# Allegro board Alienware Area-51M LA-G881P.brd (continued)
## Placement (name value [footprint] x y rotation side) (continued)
PQS10  EMZB08P03H_EDFN5X6-8-5  [AON6403_DFN5X6-8-5]  116.05 164.46 90 top
PQS11  AON6314_N_DFN56-8-5  [Q_N_DFN56-8-5]  150.6 128.97 180 top
PQS12  DMP3056L-7 1P SOT23-3  [NTR4502PT1G_SOT23-3]  113.61 171.48 270 bottom
PQS13  L2N7002DW1T1G_SC88-6  [DMN65D8LDW-7_SOT363-6]  110.84 167.19 0 bottom
PQS15  EMZB08P03H_EDFN5X6-8-5  [AON6403_DFN5X6-8-5]  137.42 150.16 90 top
PQS16  DMP3056L-7 1P SOT23-3  [NTR4502PT1G_SOT23-3]  141.62 152.96 0 bottom
PQS17  L2N7002DW1T1G_SC88-6  [DMN65D8LDW-7_SOT363-6]  147.62 151.53 270 bottom
PQS18  L2N7002WT1G 1N SC-70-3  [SSM3K7002FU_SC70-3]  128.32 152.24 0 top
PQS19  L2N7002WT1G 1N SC-70-3  [SSM3K7002FU_SC70-3]  151.96 147.75 0 top
PQS22  -  [AO3409_SOT23-3]  146.28 158.47 270 bottom
PQS23  L2N7002WT1G 1N SC-70-3  [SSM3K7002FU_SC70-3]  129.12 152.8 270 bottom
PQS24  -  [AO3409_SOT23-3]  160.35 149.98 90 top
PQS26  -  [AO3409_SOT23-3]  142.46 162.46 90 bottom
PQS27  -  [AO3409_SOT23-3]  158.78 156.04 180 top
PQS28  L2N7002WT1G 1N SC-70-3  [SSM3K7002FU_SC70-3]  154.9 152.68 180 top
PQS29  L2N7002DW1T1G_SC88-6  [2N7002DW-7-F_SOT363-6]  124.04 152.42 90 top
PQS30  L2N7002DW1T1G_SC88-6  [2N7002DW-7-F_SOT363-6]  156.34 144.98 0 top
PQS31  -  [LMUN5113T1G_SOT323-3]  126.08 132.52 0 bottom
PQS32  -  [LTC015EUBFS8TL_UMT3F]  128.78 131.48 0 bottom
PR1  100K_0402_1%  [R_0402]  156.25 164.74 180 top
PR2  15K_0402_1%  [R_0402]  154.57 164.75 180 top
PR3  33_0402_5%  [R_0402]  152.04 164.74 90 top
PR4  2.2K_0402_1%  [R_0402]  152.83 165.66 270 top
PR5  10K_0402_1%  [R_0402]  153.04 167.42 180 top
PR6  100K_0402_1%  [R_0402]  134.98 146.16 180 bottom
PR7  15K_0402_1%  [R_0402]  135.99 145.17 270 bottom
PR8  33_0402_5%  [R_0402]  133.07 151.05 180 bottom
PR9  2.2K_0402_1%  [R_0402]  131.47 149.34 90 bottom
PR10  10K_0402_1%  [R_0402]  133.13 146.18 180 bottom
PR11  100_0402_1%  [R_0402]  73.23 10.44 90 top
PR12  100_0402_1%  [R_0402]  72.26 10.44 90 top
PR13  100_0402_1%  [R_0402]  75.75 11.57 0 top
PR14  100K_0402_1%  [R_0402]  77.78 10.06 0 top
PR15  1K_0402_1%  [R_0402]  350.19 13.03 180 top
PR16  100K_0402_1%  [R_0402]  56.41 22.56 90 bottom
PR17  100K_0402_1%  [R_0402]  58.92 21.96 90 bottom
PR18  1K_0402_1%  [R_0402]  352.2 11.28 90 top
PR19  100K_0402_1%  [R_0402]  55.65 22.5 90 bottom
PR20  0_0402_5%  [R0402_0OHM]  58.15 22.88 270 bottom
PR21  100K_0402_1%  [R_0402]  150.78 158.96 0 bottom
PR22  10K_0402_1%  [R_0402]  150 158.09 90 bottom
PR23  110K_0402_1%  [R_0402]  308.2 7.46 270 top
PR24  14.7K_0402_1%  [R_0402]  309.49 27.85 270 top
PR25  14.7K_0402_1%  [R_0402]  300.86 25.57 180 bottom
PR26  100K_0402_1%  [R_0402]  306.48 7.44 270 top
PR27  0_0402_5%  [R0402_0OHM]  151.94 162.66 180 bottom
PR28  100K_0402_1%  [R_0402]  79.1 12.65 90 top
PR34  100K_0402_1%  [R_0402]  59.79 21.15 270 bottom
PR35  205K_0402_1%  [R_0402]  118.01 171.22 90 top
PR36  1M_0402_1%  [R_0402]  117.19 172.13 270 top
PR37  205K_0402_1%  [R_0402]  151.16 152.5 270 top
PR38  1M_0402_1%  [R_0402]  149.43 151.71 0 top
PR40  10K_0402_1%  [R_0402]  149.37 166.16 90 bottom
PR41  100K_0402_1%  [R_0402]  147.37 168.1 180 bottom
PR42  0_0402_5%  [R0402_0OHM]  150.18 165.29 180 bottom
PR44  0_0402_5%  [R0402_0OHM]  155.16 163.85 270 bottom
PR45  0_0402_5%  [R0402_0OHM]  150.64 169.35 90 bottom
PR101  100K_0402_1%  [R_0402]  259.66 10.75 0 top
PR102  2.2_0603_5%  [R_0603]  267.07 10.51 0 top
PR103  97.6K_0402_1%  [R_0402]  259.67 9.98 0 top
PR104  100K_0402_1%  [R_0402]  259.71 8.31 0 top
PR105  4.7_1206_5%  [R_1206]  267.04 17.17 0 bottom
PR106  470K_0402_1%  [R_0402]  261.32 5.61 0 top
PR107  4.99K_0402_1%  [R_0402]  260.61 7.53 180 top
PR108  10K_0402_1%  [R_0402]  260.58 5.93 180 top
PR200  2.2_0603_5%  [R_0603]  217.86 121.4 270 top
PR201  11K_0402_1%  [R_0402]  223.67 118.17 180 top
PR202  4.7_1206_5%  [R_1206]  240.87 113 180 top
PR203  5.1_0603_5%  [R_0603]  223.61 112.67 180 top
PR204  2.2_0603_5%  [R_0603]  223.72 116.96 180 top
PR205  12K_0402_1%  [R_0402]  213.51 115.91 0 top
PR206  887K_0402_1%  [R_0402]  219.36 113.04 90 top
PR207  20K_0402_1%  [R_0402]  213.51 115.14 0 top
PR208  0_0402_5%  [R0402_0OHM]  218.59 112.89 90 top
PR209  0_0402_5%  [R_0402]  216.04 113.78 270 top
PR210  100K_0402_1%  [R_0402]  220.13 113.03 90 top
PR211  0_0402_5%  [R0402_0OHM]  215.26 113.79 270 top
PR212  1K_0402_1%  [R_0402]  217.39 111.16 270 top
PR213  60.4K_0402_1%  [R_0402]  215.02 111.97 270 top
PR214  1K_0402_1%  [R_0402]  214.25 111.97 270 top
PR215  60.4K_0402_1%  [R_0402]  215.79 111.97 270 top
PR216  100K_0402_1%  [R_0402]  216.61 110.25 90 top
PR217  100K_0402_1%  [R_0402]  212.83 108.73 90 top
PR301  10K_0402_1%  [R_0402]  333.04 39.37 180 top
PR302  15.8K_0402_1%  [R_0402]  332.12 36.46 0 top
PR303  14.3K_0402_1%  [R_0402]  333.04 40.13 180 top
PR304  10K_0402_1%  [R_0402]  332.12 37.22 0 top
PR305  54.9K_0402_1%  [R_0402]  333.04 40.93 180 top
PR306  61.9K_0402_1%  [R_0402]  331.29 34.05 90 top
PR307  200_0402_1%  [R_0402]  330.46 34.96 270 top
PR308  0_0603_5%  [R_0603]  328.42 35.15 270 top
PR309  0_0603_5%  [R_0603]  328.41 42.76 270 top
PR310  4.7_1206_5%  [R_1206]  308.77 51.84 270 top
PR311  4.7_1206_5%  [R_1206]  312.69 32.7 180 top
PR312  0_0402_5%  [R0402_0OHM]  326.48 17.05 270 top
PR313  0_0402_5%  [R0402_0OHM]  325.72 17.05 270 top
PR314  2.2K_0402_1%  [R_0402]  324.87 15.34 0 top
PR315  0_0402_5%  [R0402_0OHM]  324.92 13.69 90 top
PR317  200K_0402_1%  [R_0402]  325.68 14.6 270 top
PR703  0.001_2512_1%  [R_2512_4P]  155.75 126.82 180 top
PR727  10.5K_0402_1%  [R_0402]  213.26 143.08 90 top
PR729  392K_0402_1%  [R_0402]  210.08 135.58 90 top
PR731  200K_0402_1%  [R_0402]  210.64 138.33 0 top
PR732  53.6K_0402_1%  [R_0402]  210.97 136.5 270 top
PR740  2_0402_5%  [R_0402]  208.18 132.34 90 top
PR741  100K_0402_1%  [R_0402]  211.43 138.14 180 bottom
PR742  2_0402_5%  [R_0402]  204.93 145.03 90 top
PR743  10_1206_5%  [R_1206]  205.13 133.56 270 top
PR745  100_0402_1%  [R_0402]  204.75 136.19 270 top
PR749  200K_0402_1%  [R_0402]  203.53 143.42 180 top
PR750  0_0402_5%  [R0402_0OHM]  209.03 145.62 0 top
PR751  200K_0402_1%  [R_0402]  202.61 142.65 0 top
PR752  365K_0402_1%  [R_0402]  209.95 146.4 180 top
PR753  255K_0402_1%  [R_0402]  211.24 143.15 180 top
PR754  100_0402_1%  [R_0402]  209.97 144.85 180 top
PR755  102K_0402_1%  [R_0402]  207.73 144.88 270 top
PR756  10K_0402_1%  [R_0402]  206.72 145.74 90 top
PR757  100K_0402_1%  [R_0402]  202.28 143.22 0 bottom
PR760  4.7_0402_5%  [R_0402]  202.46 140.58 270 top
PR761  0_0603_5%  [R0603_0OHM]  200.44 142.64 90 bottom
PR764  10K_0402_1%  [R_0402]  206.72 144.88 270 top
PR765  0.005_2512_1%  [R_2512_4P]  196.01 143.06 0 top
PR766  4.7_1206_5%  [R_1206]  191.67 150.07 90 bottom
PR769  0_0402_5%  [R0402_0OHM]  211.56 139.09 180 top
PR770  0_0402_5%  [R0402_0OHM]  211.56 139.98 180 top
PR771  0_0603_5%  [R_0603]  202.84 137.75 180 top
PR772  1_0402_5%  [R_0402]  208.94 132.34 90 top
PR773  0_0603_5%  [R_0603]  203.29 136.29 180 top
PR774  1K_0402_1%  [R_0402]  211.56 141.25 180 top
PR775  0_0402_5%  [R0402_0OHM]  211.56 142.14 180 top
PR776  0_0402_5%  [R0402_0OHM]  205.75 145.03 90 top
PR777  0_0402_5%  [R0402_0OHM]  213.97 139.98 180 top
PR779  0_0402_5%  [R0402_0OHM]  203.19 144.04 180 bottom
PR792  0_0402_5%  [R0402_0OHM]  212.5 143.99 270 top
PR793  0_0603_5%  [R_0603]  203.71 128.84 270 top
PR1201  40.2K_0402_1%  [R_0402]  352.6 53.29 0 bottom
PR1202  4.7_1206_5%  [R_1206]  360.84 49.99 180 top
PR1203  105K_0402_1%  [R_0402]  354.96 52.42 0 bottom
PR1204  12K_0402_1%  [R_0402]  355.88 51.66 180 bottom
PR1205  100K_0402_1%  [R_0402]  353.52 52.53 180 bottom
PR1206  56K_0402_1%  [R_0402]  355.88 50.67 180 bottom
PR1801  100K_0402_1%  [R_0402]  292.58 34.12 180 bottom
PR1802  1M_0402_1%  [R_0402]  293.15 33.17 180 bottom
PR1803  100K_0402_1%  [R_0402]  293.1 30.45 90 bottom
PR1804  24.9K_0402_1%  [R_0402]  301.42 33.92 270 bottom
PR1805  20K_0402_1%  [R_0402]  301.42 32.26 270 bottom
PR1806  2.2_0402_1%  [R_0402]  239.88 11.78 90 bottom
PR2501  0_0402_5%  [R0402_0OHM]  244.61 18.06 0 bottom
PR2502  1M_0402_1%  [R_0402]  242.94 18.14 270 bottom
PR2503  100K_0402_1%  [R_0402]  242.92 19.77 270 bottom
PR2504  21.5K_0402_1%  [R_0402]  234.63 16.81 90 bottom
PR2505  10K_0402_1%  [R_0402]  234.63 18.45 90 bottom
PR2506  2.2_0402_1%  [R_0402]  240.69 11.78 90 bottom
PRA01  2.2_0402_1%  [R_0402]  130.68 112.77 270 bottom
PRA02  10K_0402_1%  [R_0402]  126.22 115.68 180 bottom
PRA03  2.2_0603_1%  [R_0603]  133.92 114.48 180 bottom
PRA04  4.7_1206_5%  [R_1206]  145.69 121.4 0 bottom
PRA05  14K_0402_1%  [R_0402]  125.96 117.62 270 bottom
PRA06  12.1K_0402_1%  [R_0402]  135.56 111.55 0 bottom
PRA07  2K_0402_1%  [R_0402]  128.53 120.64 180 bottom
PRA08  1.82K_0402_1%  [R_0402]  127.62 119.87 0 bottom
PRA09  13K_0402_1%  [R_0402]  125.15 118.5 270 bottom
PRA10  2K_0402_1%  [R_0402]  126.22 114.88 180 bottom
PRA11  1.82K_0402_1%  [R_0402]  125.32 114.12 0 bottom
PRA12  12K_0402_1%  [R_0402]  125.94 119.24 270 bottom
PRA13  12.1K_0402_1%  [R_0402]  135.53 114.32 90 bottom
PRA14  0_0402_5%  [R_0402]  132.87 118.51 180 bottom
PRA15  270K_0402_1%  [R_0402]  124.27 119.25 0 bottom
PRA16  0_0402_5%  [R_0402]  131.95 119.3 0 bottom
PRA17  100_0402_1%  [R_0402]  128.36 112.37 270 bottom
PRA18  10_0402_1%  [R_0402]  127.25 113.14 0 bottom
PRA19  0_0402_5%  [R0402_0OHM]  127.44 112.38 270 bottom
PRA20  10K_0402_1%  [R_0402]  132.87 117.73 180 bottom
PRA21  0_0402_5%  [R0402_0OHM]  126.67 112.38 270 bottom
PRA22  100_0402_1%  [R_0402]  125.91 112.38 270 bottom
PRA23  0_0402_5%  [R0402_0OHM]  130.83 117.68 90 top
PRB66  0_0603_5%  [R_0603]  202.42 126.34 0 top
PRF01  0_0402_5%  [R0402_0OHM]  158.74 117.05 180 bottom
PRF02  10K_0402_1%  [R_0402]  157.01 116.31 270 bottom
PRF03  0_0603_5%  [R_0603]  152.5 111.91 180 bottom
PRF04  4.7_1206_5%  [R_1206]  152.17 109.3 270 bottom
PRF05  100_0402_5%  [R_0402]  162.15 110.54 0 bottom
PRF06  1M_0402_1%  [R_0402]  157.83 116.27 0 bottom
PRF07  21K_0402_1%  [R_0402]  158.26 111.42 90 bottom
PRF08  0_0402_5%  [R0402_0OHM]  163.87 110.51 0 bottom
PRF09  0_0402_5%  [R_0402]  158.31 113.45 90 bottom
PRF10  35.7K_0402_1%  [R_0402]  159.08 112.33 270 bottom
PRF11  0_0402_5%  [R_0402]  159.13 114.36 270 bottom
PRG01  0_0402_5%  [R0402_0OHM]  129.93 11.96 90 top
PRG02  1_0402_5%  [R_0402]  132.66 15.18 180 bottom
PRG03  1_0402_5%  [R_0402]  131.74 13.61 0 bottom
PRG04  10K_0402_1%  [R_0402]  131.74 14.37 0 bottom
PRG05  0_0402_5%  [R0402_0OHM]  129.17 11.97 90 top
PRG06  2.2_0603_1%  [R_0603]  125.9 11.54 90 bottom
PRG07  4.7_1206_5%  [R_1206]  133.95 14.31 0 bottom
PRG08  3.65K_0603_1%  [R_0603]  140.18 17.8 270 bottom
PRG09  100K_0402_1%  [R_0402]  141.17 15.97 90 bottom
PRG10  20M_0402_5%  [R_0402]  142.44 20.04 180 bottom
PRG11  10_0402_1%  [R_0402]  139.96 20.35 90 bottom
PRG12  100K_0402_1%  [R_0402]  141.93 15.97 90 bottom
PRG13  1_0402_5%  [R_0402]  152.93 13.98 90 bottom
PRG14  0_0402_5%  [R0402_0OHM]  150.15 12.31 90 bottom
PRG15  1_0402_5%  [R_0402]  148.41 13.21 270 bottom
PRG16  10K_0402_1%  [R_0402]  151.22 14.13 0 bottom
PRG17  0_0402_5%  [R0402_0OHM]  149.37 12.3 90 bottom
PRG18  2.2_0603_1%  [R_0603]  146.09 11.69 90 bottom
PRG19  4.7_1206_5%  [R_1206]  159.11 15.77 0 bottom
PRG20  3.65K_0603_1%  [R_0603]  159.05 19.91 270 bottom
PRG21  100K_0402_1%  [R_0402]  160.05 18.38 90 bottom
PRG22  10_0402_1%  [R_0402]  158.93 20.76 90 bottom
PRG23  100K_0402_1%  [R_0402]  160.81 18.38 90 bottom
PRI11  1_0402_5%  [R_0402]  103.33 32.05 0 top
PRI12  1_0402_5%  [R_0402]  102.44 32.37 180 bottom
PRI13  0_0402_5%  [R0402_0OHM]  101.53 30.81 0 bottom
PRI14  10K_0402_1%  [R_0402]  104.25 31.15 180 top
PRI15  0_0402_5%  [R0402_0OHM]  101.53 31.58 0 bottom
PRI16  2.2_0603_1%  [R_0603]  100.92 34.63 0 bottom
PRI17  10_1206_5%  [R_1206]  109.31 35.2 270 top
PRI18  7.5K_0603_1%  [R_0603]  111 31.69 0 top
PRI19  200K_0402_1%  [R_0402]  112.5 32.69 180 top
PRI20  10_0402_1%  [R_0402]  122.99 51.9 270 top
PRI22  200K_0402_1%  [R_0402]  112.45 34.35 270 top
PRI23  200K_0402_1%  [R_0402]  111.67 34.96 270 top
PRI27  1_0402_5%  [R_0402]  103.33 22.86 0 top
PRI28  0_0402_5%  [R0402_0OHM]  101.46 20.95 0 bottom
PRI29  1_0402_5%  [R_0402]  102.37 22.49 180 bottom
PRI30  10K_0402_1%  [R_0402]  104.25 22.08 180 top
PRI31  0_0402_5%  [R0402_0OHM]  101.46 21.73 0 bottom
PRI32  2.2_0603_1%  [R_0603]  100.86 25.61 0 bottom
PRI33  7.5K_0603_1%  [R_0603]  111.15 26.19 45 top
PRI34  200K_0402_1%  [R_0402]  112.5 28.37 180 top
PRI35  10_1206_5%  [R_1206]  107.85 22.38 270 top
PRI36  10_0402_1%  [R_0402]  124.15 26.13 270 top
PRI37  200K_0402_1%  [R_0402]  112.45 30.08 270 top
PRI38  200K_0402_1%  [R_0402]  111.67 30.08 270 top
PRI52  1_0402_5%  [R_0402]  106.08 58.44 0 top
PRI53  0_0402_5%  [R0402_0OHM]  105.12 57.3 0 bottom
PRI54  1_0402_5%  [R_0402]  106.03 58.85 180 bottom
PRI55  10K_0402_1%  [R_0402]  106.99 57.68 180 top
PRI56  0_0402_5%  [R0402_0OHM]  105.12 58.07 0 bottom
PRI57  2.2_0603_1%  [R_0603]  104.48 61.66 0 bottom
PRI58  10_1206_5%  [R_1206]  114.73 60.72 90 bottom
PRI59  7.5K_0603_1%  [R_0603]  118.86 61.87 270 top
PRI60  200K_0402_1%  [R_0402]  117.65 60.84 90 top
PRI61  10_0402_1%  [R_0402]  119.07 64.51 270 top
PRI62  200K_0402_1%  [R_0402]  117.64 62.75 90 top
PRI63  200K_0402_1%  [R_0402]  117.63 65.54 90 top
PRI67  1_0402_5%  [R_0402]  107.29 68.02 0 bottom
PRI68  0_0402_5%  [R0402_0OHM]  106.26 69.57 0 bottom
PRI69  1_0402_5%  [R_0402]  104.49 71.83 90 bottom
PRI70  10K_0402_1%  [R_0402]  106.46 68.81 270 bottom
PRI71  0_0402_5%  [R0402_0OHM]  106.26 70.34 0 bottom
PRI72  2.2_0603_1%  [R_0603]  106.33 73.42 0 bottom
PRI73  10_1206_5%  [R_1206]  118.29 73.57 90 top
PRI74  7.5K_0603_1%  [R_0603]  118.41 68.57 90 top
PRI75  200K_0402_1%  [R_0402]  118.63 70.82 180 top
PRI76  10_0402_1%  [R_0402]  119.02 66.81 90 top
PRI77  200K_0402_1%  [R_0402]  117.72 71.74 0 top
PRI78  200K_0402_1%  [R_0402]  117.72 72.51 0 top
PRI92  1_0402_5%  [R_0402]  103.54 41.17 0 top
PRI93  0_0402_5%  [R0402_0OHM]  101.66 40.66 0 bottom
PRI94  1_0402_5%  [R_0402]  102.57 42.23 180 bottom
PRI95  10K_0402_1%  [R_0402]  104.45 40.24 180 top
PRI96  0_0402_5%  [R0402_0OHM]  101.66 41.44 0 bottom
PRI97  2.2_0603_1%  [R_0603]  101.05 44.46 0 bottom
PRI98  10_1206_5%  [R_1206]  109.13 43.36 270 top
PRI99  7.5K_0603_1%  [R_0603]  112.3 39.4 90 top
PRI100  200K_0402_1%  [R_0402]  112.53 38.53 180 top
PRI101  10_0402_1%  [R_0402]  122.19 51.9 270 top
PRI102  200K_0402_1%  [R_0402]  112.53 37.63 180 top
PRI103  200K_0402_1%  [R_0402]  112.53 36.85 180 top
PRI107  1_0402_5%  [R_0402]  104.34 49.62 0 top
PRI108  0_0402_5%  [R0402_0OHM]  102.96 49.37 0 bottom
PRI109  1_0402_5%  [R_0402]  103.87 50.94 180 bottom
PRI110  10K_0402_1%  [R_0402]  105.26 48.85 180 top
PRI111  0_0402_5%  [R0402_0OHM]  102.96 50.15 0 bottom
PRI112  2.2_0603_1%  [R_0603]  102.6 53.2 0 bottom
PRI113  10_1206_5%  [R_1206]  112.26 51.4 90 bottom
PRI114  7.5K_0603_1%  [R_0603]  118.18 55.44 90 top
PRI115  200K_0402_1%  [R_0402]  118.53 57.81 180 top
PRI116  10_0402_1%  [R_0402]  118.86 53.68 135 top
PRI117  200K_0402_1%  [R_0402]  117.69 59.47 270 top
PRI118  200K_0402_1%  [R_0402]  118.45 59.47 270 top
PRI201  698_0402_1%  [R_0402]  89.05 29.22 180 top
PRI202  30.1K_0402_1%  [R_0402]  82.33 28.15 180 bottom
PRI203  100_0402_1%  [R_0402]  88.56 25.87 180 bottom
PRI204  698_0402_1%  [R_0402]  89.23 26.75 180 top
PRI205  0_0402_5%  [R0402_0OHM]  83.22 26.03 0 bottom
PRI206  0_0402_5%  [R0402_0OHM]  89.2 27.58 180 bottom
PRI207  15K_0402_1%  [R_0402]  82.33 27.39 180 bottom
PRI208  10K_0402_1%  [R_0402]  83.66 28.57 270 top
PRI209  0_0402_5%  [R0402_0OHM]  83.24 30.21 0 bottom
PRI210  100_0402_1%  [R_0402]  89.07 28.36 180 bottom
PRI211  698_0402_1%  [R_0402]  89.11 41.18 180 top
PRI212  0_0402_5%  [R0402_0OHM]  83.27 44.36 0 bottom
PRI213  0_0402_5%  [R0402_0OHM]  89.11 41.91 180 bottom
PRI214  15K_0402_1%  [R_0402]  82.28 41.26 270 bottom
PRI215  100_0402_1%  [R_0402]  88.3 40.16 180 bottom
PRI216  30.1K_0402_1%  [R_0402]  82.29 42 180 bottom
PRI217  10K_0402_1%  [R_0402]  83.68 42.72 270 top
PRI218  698_0402_1%  [R_0402]  89.07 43.77 180 top
PRI219  0_0402_5%  [R0402_0OHM]  83.22 40.18 0 bottom
PRI220  100_0402_1%  [R_0402]  89.11 42.68 180 bottom
PRI221  100_0402_1%  [R_0402]  89.01 36.31 180 bottom
PRI222  0_0402_5%  [R0402_0OHM]  83.11 33.8 0 bottom
PRI223  698_0402_1%  [R_0402]  89.01 34.95 180 top
PRI224  0_0402_5%  [R0402_0OHM]  83.17 37.98 0 bottom
PRI225  0_0402_5%  [R0402_0OHM]  89.01 35.53 180 bottom
PRI226  15K_0402_1%  [R_0402]  82.15 34.72 180 bottom
PRI227  100_0402_1%  [R_0402]  88.98 33.83 180 bottom
PRI228  30.1K_0402_1%  [R_0402]  82.14 35.65 180 bottom
PRI229  10K_0402_1%  [R_0402]  83.58 36.34 270 top
PRI230  698_0402_1%  [R_0402]  89.01 37.17 180 top
PRS01  0.005_2512_1%  [R_2512_4P]  108.89 160.89 90 top
PRS02  1_0402_1%  [R_0402]  121.23 146.57 0 bottom
PRS03  1_0402_1%  [R_0402]  121.23 145.79 0 bottom
PRS04  2.2_0603_5%  [R_0603]  122.42 143.88 180 bottom
PRS06  0_0805_5%  [R_0805]  120.9 148.05 0 bottom
PRS08  10_1206_5%  [R_1206]  124.38 151.97 270 bottom
PRS09  4.7_0402_5%  [R_0402]  124.05 141.56 270 bottom
PRS10  0_0402_5%  [R0402_0OHM]  126.52 149.67 270 bottom
PRS11  2.2_0603_5%  [R_0603]  125.49 139.73 90 bottom
PRS12  0_0402_5%  [R0402_0OHM]  127.28 149.67 270 bottom
PRS13  0_0402_5%  [R0402_0OHM]  126.81 143.25 0 top
PRS14  2.2K_0402_1%  [R_0402]  128.6 149.71 270 top
PRS15  2.2K_0402_1%  [R_0402]  127.84 149.71 270 top
PRS18  182K_0402_1%  [R_0402]  127.07 145.72 0 top
PRS19  0_0402_5%  [R0402_0OHM]  129.82 143.85 270 bottom
PRS20  698_0402_1%  [R_0402]  129.79 145.54 0 bottom
PRS21  0.005_2512_1%  [R_2512_4P]  132.36 146.63 90 top
PRS22  1_0402_1%  [R_0402]  143.2 143.7 0 bottom
PRS23  1_0402_1%  [R_0402]  143.2 142.92 0 bottom
PRS24  2.2_0603_5%  [R_0603]  144.55 140.98 180 bottom
PRS26  0_0805_5%  [R_0805]  144.93 144.93 180 bottom
PRS29  4.7_0402_5%  [R_0402]  146.23 139.04 270 bottom
PRS30  0_0402_5%  [R0402_0OHM]  148.64 147.28 270 bottom
PRS31  2.2_0603_5%  [R_0603]  149.15 137.89 180 bottom
PRS32  0_0402_5%  [R0402_0OHM]  149.4 147.28 270 bottom
PRS33  0_0402_5%  [R0402_0OHM]  149.26 140.69 0 top
PRS34  2.2K_0402_1%  [R_0402]  150.72 147.25 270 top
PRS35  2.2K_0402_1%  [R_0402]  149.96 147.26 270 top
PRS38  182K_0402_1%  [R_0402]  149.63 143.18 0 top
PRS39  0_0402_5%  [R0402_0OHM]  152.28 141.39 270 bottom
PRS40  698_0402_1%  [R_0402]  153.22 143.04 180 bottom
PRS41  10_1206_5%  [R_1206]  143.22 147.28 0 bottom
PRS53  200K_0402_1%  [R_0402]  128.54 148.71 90 bottom
PRS54  100K_0402_1%  [R_0402]  128.22 147.32 180 top
PRS55  200K_0402_1%  [R_0402]  150.66 146.37 90 bottom
PRS56  100K_0402_1%  [R_0402]  150.7 144.55 180 top
PRS57  169K_0402_1%  [R_0402]  113.25 165.68 90 bottom
PRS58  100K_0402_1%  [R_0402]  112.35 164.34 180 bottom
PRS59  1M_0402_5%  [R_0402]  114.48 168.48 90 bottom
PRS60  100K_0402_1%  [R_0402]  112.29 169.07 270 bottom
PRS61  1M_0402_5%  [R_0402]  115.69 171.78 90 bottom
PRS62  20K_0402_1%  [R_0402]  111.48 168.23 180 bottom
PRS63  200K_0402_1%  [R_0402]  110.57 169.06 0 bottom
PRS64  100K_0402_1%  [R_0402]  144.02 151.23 270 bottom
PRS65  20K_0402_1%  [R_0402]  148.55 150.82 90 bottom
PRS66  100K_0402_1%  [R_0402]  144.82 150.31 90 bottom
PRS67  1M_0402_5%  [R_0402]  139.19 152.39 90 bottom
PRS68  1M_0402_5%  [R_0402]  137.9 154.35 0 bottom
PRS69  169K_0402_1%  [R_0402]  149.38 151.74 270 bottom
PRS70  200K_0402_1%  [R_0402]  144.87 152.04 180 bottom
PRS73  0_0402_5%  [R0402_0OHM]  126.06 149.8 270 top
PRS74  0_0402_5%  [R0402_0OHM]  148.16 147.29 270 top
PRS75  1M_0402_5%  [R_0402]  126.69 151.94 270 top
PRS76  49.9K_0402_1%  [R_0402]  127.46 151.03 90 top
PRS77  100K_0402_1%  [R_0402]  129.95 153.59 270 top
PRS78  100K_0402_1%  [R_0402]  152.7 150.77 180 top
PRS79  49.9K_0402_1%  [R_0402]  152.83 147.34 0 top
PRS80  1M_0402_5%  [R_0402]  153.62 149.07 270 top
PRS83  4.7_1206_5%  [R_1206]  113.16 142.71 270 top
PRS85  4.7_1206_5%  [R_1206]  146.9 138.33 0 top
PRS86  1M_0402_5%  [R_0402]  142.37 159.69 270 bottom
PRS87  1M_0402_5%  [R_0402]  142.39 158.01 270 bottom
PRS89  1M_0402_5%  [R_0402]  156.49 148.97 90 top
PRS90  1M_0402_5%  [R_0402]  156.49 150.65 90 top
PRS92  0_0402_5%  [R_0402]  126.01 152.55 270 bottom
PRS93  0_0402_5%  [R_0402]  155.48 148.36 90 top
PRS94  10K_0402_1%  [R_0402]  126.12 154.4 180 top
PRS95  10K_0402_1%  [R_0402]  154.11 143.99 0 top
PRS96  0_0603_5%  [R_0603]  125.37 133.79 0 bottom
PRS97  0_0603_5%  [R_0603]  128.01 134.33 90 bottom
PRS98  0_0402_5%  [R_0402]  204.69 130.12 90 bottom
PRS99  0_0402_5%  [R_0402]  210.52 137.37 0 bottom
PRZ01  45.3_0402_1%  [R_0402]  57.04 29.84 0 bottom
PRZ02  0_0402_5%  [R0402_0OHM]  59.26 29.04 0 top
PRZ03  1_0402_5%  [R_0402]  59.27 32.15 0 top
PRZ04  0_0402_5%  [R0402_0OHM]  60.17 32.92 180 top
PRZ05  75_0402_1%  [R_0402]  57.04 30.62 0 bottom
PRZ06  100_0402_1%  [R_0402]  57.03 31.39 0 bottom
PRZ07  0_0402_5%  [R0402_0OHM]  57.95 29.87 180 top
PRZ08  49.9_0402_1%  [R_0402]  59.26 29.83 0 top
PRZ09  0_0402_5%  [R0402_0OHM]  57.95 30.63 180 top
PRZ10  0_0402_5%  [R0402_0OHM]  59.26 30.62 0 top
PRZ11  95.3K_0402_1%  [R_0402]  61.25 25.58 90 bottom
PRZ12  0_0402_5%  [R0402_0OHM]  57.95 31.39 180 top
PRZ13  10_0402_1%  [R_0402]  59.26 31.38 0 top
PRZ14  27.4K_0402_1%  [R_0402]  62.09 23.68 90 bottom
PRZ15  12.4K_0402_1%  [R_0402]  61.96 25.61 90 top
PRZ16  1.91K_0402_1%  [R_0402]  59.25 28.28 0 top
PRZ17  150K_0402_1%  [R_0402]  60.17 36.03 180 top
PRZ18  9.31K_0402_1%  [R_0402]  60.17 35.27 180 top
PRZ19  48.7K_0402_1%  [R_0402]  60.18 34.46 180 top
PRZ20  210K_0402_1%  [R_0402]  60.17 33.69 180 top
PRZ21  0_0402_5%  [R0402_0OHM]  59.26 28.28 0 bottom
PRZ22  2K_0402_1%  [R_0402]  62.87 26.5 0 bottom
PRZ23  2K_0402_1%  [R_0402]  65.58 26.59 270 top
PRZ24  0_0402_5%  [R0402_0OHM]  59.26 27.51 0 top
PRZ25  316_0402_1%  [R_0402]  64.76 25.66 90 top
PRZ26  0_0402_5%  [R0402_0OHM]  59.26 26.73 0 top
PRZ27  48.7K_0402_1%  [R_0402]  63.92 34.47 270 bottom
PRZ28  2.8K_0402_1%  [R_0402]  64.71 24.88 270 bottom
PRZ29  4.42K_0402_1%  [R_0402]  140.77 19.94 270 bottom
PRZ30  11K_0402_1%  [R_0402]  68.29 25.43 270 top
PRZ31  1K_0402_1%  [R_0402]  67.42 25.28 90 top
PRZ32  243_0402_1%  [R_0402]  66.51 25.28 90 top
PRZ33  523_0402_1%  [R_0402]  70.07 32.7 0 bottom
PRZ34  11K_0402_1%  [R_0402]  72 35.34 0 top
PRZ35  1K_0402_1%  [R_0402]  72.01 32.61 90 top
PRZ36  2.61K_0402_1%  [R_0402]  115.23 22.95 180 bottom
PRZ37  12.4K_0402_1%  [R_0402]  70.98 29.51 180 top
PRZ38  1K_0402_1%  [R_0402]  70.08 31.88 0 top
PRZ39  76.8K_0402_1%  [R_0402]  70.07 28.75 0 top
PRZ40  27.4K_0402_1%  [R_0402]  72.99 29.14 180 top
PRZ41  2K_0402_1%  [R_0402]  70.08 31.1 0 top
PRZ42  6.04K_0402_1%  [R_0402]  71.03 31.07 180 bottom
PRZ43  1.27K_0402_1%  [R_0402]  70.09 30.32 0 top
PRZ44  0_0402_5%  [R0402_0OHM]  64.06 35.91 0 top
PRZ45  20M_0402_5%  [R_0402]  72.91 32.61 90 top
PU101  -  [TPS51212DSCR_SON10_3X3]  262.03 10.34 270 top
PU201  -  [RT8207PGQW_WQFN20_3X3]  216.87 117.68 270 top
PU301  -  [TPS51225CRUKR_QFN20_3X3]  330.58 37.53 90 top
PU703  ISL88739AHRZ-T_QFN32_4X4  [ISL95520HRZ-T_QFN32_4X4]  209.08 138.58 180 top
PU1201  -  [RT9297GQW_WDFN10_3X3]  357.33 52.7 0 bottom
PU1801  -  [RT9059GSP_SO8]  294.74 31.53 90 bottom
PU2501  -  [RT9059GSP_SO8]  241.35 18.57 270 bottom
PUA01  -  [ISL95870BHRZ-T_QFN20_3X4]  127.62 115.21 90 bottom
PUF01  -  [SY8286RAC_QFN20_3X3]  153.88 111.58 0 bottom
PUG01  -  [SIC632CDT1GE3_POWERPAK31_5X5]  129.77 14.27 90 bottom
PUG02  -  [SIC632CDT1GE3_POWERPAK31_5X5]  149.22 14.57 90 bottom
PUI01  -  [SIC632CDT1GE3_POWERPAK31_5X5]  103.87 32.06 0 bottom
PUI02  -  [SIC632CDT1GE3_POWERPAK31_5X5]  104.08 23.09 0 bottom
PUI03  -  [SIC632CDT1GE3_POWERPAK31_5X5]  107.35 58.55 0 bottom
PUI04  -  [SIC632CDT1GE3_POWERPAK31_5X5]  109.49 69.77 0 bottom
PUI05  -  [SIC632CDT1GE3_POWERPAK31_5X5]  103.9 41.29 0 bottom
PUI06  -  [SIC632CDT1GE3_POWERPAK31_5X5]  105.35 49.66 0 bottom
PUI07  -  [ISL6617CRZ-T_DFN10_3X3]  86.61 29.11 180 bottom
PUI08  -  [ISL6617CRZ-T_DFN10_3X3]  86.56 43.28 180 bottom
PUI09  -  [ISL6617CRZ-T_DFN10_3X3]  86.44 36.88 180 bottom
PUS1  -  [ISL95338HRTZ-T_TQFN32_4X4]  127.59 143.23 90 bottom
PUS2  -  [ISL95338HRTZ-T_TQFN32_4X4]  149.97 140.72 90 bottom
PUZ01  -  [ISL95829CHRTZ-T_TQFN48_6X6]  62.76 28.59 90 top
Q7  DMN66D0LDW-7_SOT363-6  [DMN65D8LDW-7_SOT363-6]  293.63 22.41 0 bottom
Q8  DMN66D0LDW-7_SOT363-6  [DMN65D8LDW-7_SOT363-6]  296.45 22.41 0 bottom
Q9  DMN66D0LDW-7_SOT363-6  [DMN65D8LDW-7_SOT363-6]  210.3 103.34 180 top
Q2407  -  [MMBT3904WH_SOT323-3]  116.13 81.87 180 bottom
Q2409  -  [AO6424A_TSOP6]  88.25 22.18 0 top
Q2410  L2N7002WT1G 1N SC-70-3  [SSM3K7002FU_SC70-3]  87.06 18.26 270 top
Q2411  -  [MMBT3904WH_SOT323-3]  370.49 16.28 0 bottom
Q2412  -  [MMBT3904WH_SOT323-3]  18.54 10.4 0 bottom
QE1  -  [DMN66D0LDW-7_SOT363-6]  354.34 42.91 270 top
QE2  2N7002W-T/R7_SOT323-3  [2N7002W-T-R7_SOT323-3]  304.9 31.43 180 top
QE3  -  [DMN66D0LDW-7_SOT363-6]  351.98 39.61 180 top
QE4  -  [DMN66D0LDW-7_SOT363-6]  349.11 35.29 0 bottom
QE5  DMN66D0LDW-7_SOT363-6~D  [DMN66D0LDW-7_SOT363-6]  239.84 10.27 90 top
QE8  LP2301ALT1G 1P SOT-23-3  [SI2301CDS-T1-GE3_SOT23-3]  180.36 187.58 90 top
QE13  DMN66D0LDW-7_SOT363-6~D  [DMN66D0LDW-7_SOT363-6]  158.82 168.64 90 top
QE21  DMN66D0LDW-7_SOT363-6~D  [DMN66D0LDW-7_SOT363-6]  153.88 169.88 270 top
QE22  DMN66D0LDW-7_SOT363-6~D  [DMN66D0LDW-7_SOT363-6]  153.14 172.38 270 top
QE58  2N7002W-T/R7_SOT323-3  [2N7002W-T-R7_SOT323-3]  240.55 6.32 270 top
QE59  2N7002W-T/R7_SOT323-3  [2N7002W-T-R7_SOT323-3]  354.85 46 90 top
QE64  DMN66D0LDW-7_SOT363-6~D  [DMN66D0LDW-7_SOT363-6]  313.92 22.88 180 top
QE65  2N7002W-T/R7_SOT323-3  [2N7002W-T-R7_SOT323-3]  44.58 15.58 90 top
QH1  -  [MESS138W-G_SOT323-3]  282.79 88.98 180 bottom
QH5  DMN66D0LDW-7  [DMN66D0LDW-7_SOT363-6]  279.08 75.32 270 top
QM1  LP2301ALT1G 1P SOT-23-3  [SI2301CDS-T1-GE3_SOT23-3]  165.71 192 270 bottom
QM2  -  [DMN66D0LDW-7_SOT363-6]  158.99 191.22 90 bottom
QM3  LP2301ALT1G 1P SOT-23-3  [SI2301CDS-T1-GE3_SOT23-3]  165.63 188.01 270 bottom
QN8  -  [L2N7002DW1T1G_SC88-6]  355.69 37.57 270 bottom
QN9  -  [L2N7002DW1T1G_SC88-6]  353.47 41.5 270 bottom
QS3  -  [L2N7002WT1G_SC-70-3]  254.66 14 180 top
QT2  DMN66D0LDW-7_SOT363-6~D  [DMN66D0LDW-7_SOT363-6]  83.63 8.06 90 top
R174  10K_0402_5%  [R_0402]  337.22 21.83 0 top
R179  300K_0402_5%~D  [R_0402]  86.79 19.15 180 top
R180  1.5M_0402_5%~D  [R_0402]  86.79 20.88 180 top
R181  10K_0402_5%  [R_0402]  215.95 105.74 0 bottom
R182  0_0402_5%  [R_0402]  337.17 21.04 0 top
R185  0_0402_5%  [R0402_0OHM]  218.85 104.01 0 bottom
R307  100K_0402_1%  [R_0402]  294.28 18.64 90 bottom
R325  100K_0402_1%  [R_0402]  209.73 100.43 0 top
R363  10K_0201_5%  [R_0201]  366.44 24.41 0 bottom
R365  10K_0201_5%  [R_0201]  371.55 14.69 90 bottom
R367  10K_0402_5%  [R_0402]  274.54 84.78 90 top
R369  4.99K_0402_1%  [R_0402]  26.89 26.3 90 top
R370  0_0402_5%  [R_0402]  34.82 25.96 180 top
R371  4.7K_0402_5%  [R_0402]  29.79 19.56 90 top
R372  4.7K_0402_5%  [R_0402]  30.61 19.56 90 top
R373  4.7K_0402_5%  [R_0402]  31.65 19.56 90 top
R374  4.7K_0402_5%  [R_0402]  32.66 19.56 90 top
R375  4.7K_0402_5%  [R_0402]  28.78 19.56 90 top
R376  4.7K_0402_5%  [R_0402]  29.06 28.85 270 top
R377  4.7K_0402_5%  [R_0402]  29.84 28.85 270 top
R378  4.7K_0402_5%  [R_0402]  30.89 28.85 270 top
R379  4.7K_0402_5%  [R_0402]  27.25 28.88 270 top
R393  2K_0402_5%  [R_0402]  28.04 28.88 270 top
R394  0_0402_5%  [R_0402]  119.99 86.74 0 bottom
R395  0_0402_5%  [R_0402]  121.41 83.64 0 bottom
R396  0_0402_5%  [R_0402]  135.78 27.84 0 top
R397  0_0402_5%  [R_0402]  130.17 25.2 90 top
R398  0_0402_5%  [R_0402]  133.96 30.88 270 top
R399  4.7K_0402_5%  [R_0402]  32.44 17.19 90 top
R400  4.7K_0402_5%  [R_0402]  31.62 17.19 90 top
R402  4.7K_0402_5%  [R_0402]  29.06 31.24 270 top
R403  4.7K_0402_5%  [R_0402]  29.84 31.24 270 top
R404  4.7K_0402_5%  [R_0402]  30.91 31.24 270 top
R405  4.7K_0402_5%  [R_0402]  27.18 31.27 270 top
R406  4.7K_0402_5%  [R_0402]  29.77 17.19 90 top
R407  4.7K_0402_5%  [R_0402]  30.58 17.19 90 top
R408  4.7K_0402_5%  [R_0402]  121.94 6.78 0 bottom
R409  4.7K_0402_5%  [R_0402]  121.94 7.62 0 bottom
R410  4.7K_0402_5%  [R_0402]  113.64 9.6 90 bottom
R411  4.7K_0402_5%  [R_0402]  25.99 19.2 0 top
R412  0_0402_5%  [R0402_0OHM]  225.53 106.07 180 bottom
RC1  30_0402_5%  [R_0402]  141.33 104.87 270 bottom
RC2  1K_0402_1%  [R_0402]  119.13 83.64 0 bottom
RC3  1K_0402_1%  [R_0402]  134.72 28.34 90 top
RC4  499_0402_1%  [R_0402]  134.72 29.97 90 top
RC5  20_0402_1%  [R_0402]  120.65 84.88 180 top
RC9  1K_0402_5%  [R_0402]  56.72 37.89 90 top
RC10  24.9_0402_1%  [R_0402]  142.34 74.95 180 top
RC11  43_0402_1%  [R_0402]  121.79 86.74 90 bottom
RC12  1K_0402_5%  [R_0402]  139.72 103.96 90 bottom
RC13  60.4_0402_1%  [R_0402]  140.54 104.87 270 bottom
RC14  24.9_0402_1%  [R_0402]  142.01 75.94 180 top
RC16  56_0402_1%  [R_0402]  135.78 28.6 0 top
RC17  100_0402_1%  [R_0402]  133.96 28.34 90 top
RC19  220_0402_1%  [R_0402]  135.78 27.07 0 top
RC21  0_0402_5%  [R_0402]  154.91 76.12 90 top
RC25  0_0402_5%  [R_0402]  154.89 73.73 0 top
RC26  49.9_0402_1%  [R_0402]  141.2 74.07 0 top
RC35  51_0402_1%  [R_0402]  54.58 47.39 135 top
RC36  20_0402_5%  [R_0402]  121.92 88.8 0 bottom
RC62  49.9K_0402_1%  [R_0402]  282.7 73.96 90 top
RC63  49.9K_0402_1%  [R_0402]  283.49 73.96 90 top
RC197  100_0402_1%  [R_0402]  127.71 26.11 0 top
RC348  51_0402_1%  [R_0402]  53.97 46.78 135 top
RC353  1K_0402_5%  [R_0402]  57.56 37.89 90 top
RC354  1K_0402_1%  [R_0402]  58.44 38.81 270 top
RC355  1K_0402_1%  [R_0402]  55.27 41.45 180 top
RC356  0_0402_5%  [R_0402]  176.81 32.08 90 top
RC684  0_0402_5%  [R_0402]  173.3 30.35 270 top
RC685  0_0402_5%  [R_0402]  172.49 30.33 270 top
RC686  100_0402_1%  [R_0402]  129.39 26.11 270 top
RC687  51_0402_1%  [R_0402]  55.22 42.26 180 top
RC688  1.5K_0402_5%  [R_0402]  60.87 37.93 180 top
RC690  100_0402_1%  [R_0402]  135.91 30.9 270 top
RC691  100_0402_1%  [R_0402]  136.68 29.98 90 top
RC692  30_0402_5%  [R_0402]  121.87 93.24 0 bottom
RC693  51_0402_1%  [R_0402]  121.68 85.3 0 bottom
RD1  0_0402_5%  [R_0402]  256.82 86.48 0 top
RD2  0_0402_5%  [R_0402]  256.82 87.25 0 top
RD3  0_0402_5%  [R_0402]  255.85 69.87 0 top
RD4  0_0402_5%  [R_0402]  257.73 85.72 180 top
RD5  0_0402_5%  [R_0402]  257.73 88.01 180 top
RD6  0_0402_5%  [R_0402]  256.77 70.64 180 top
RD7  240_0402_1%  [R_0402]  256.69 83.64 180 top
RD8  1K_0402_1%  [R_0402]  252.65 68.1 270 top
RD9  2_0402_1%  [R_0402]  253.44 68.1 0 top
RD10  1K_0402_1%  [R_0402]  253.57 68.91 180 top
RD11  24.9_0402_1%  [R_0402]  255.65 68.27 0 top
RD12  0_0402_5%  [R_0402]  241.58 93.93 90 top
RD13  0_0402_5%  [R_0402]  241.58 96.49 270 top
RD14  0_0402_5%  [R_0402]  242.59 72.51 180 top
RD15  0_0402_5%  [R_0402]  240.77 94.84 270 top
RD16  0_0402_5%  [R_0402]  240.77 95.58 90 top
RD17  0_0402_5%  [R_0402]  241.12 70.91 0 top
RD18  240_0402_1%  [R_0402]  242.8 59.74 180 top
RD26  0_0402_5%  [R_0402]  224.97 93.17 0 top
RD27  0_0402_5%  [R_0402]  224.21 94.59 90 top
RD28  0_0402_5%  [R_0402]  226.53 70.09 0 top
RD29  0_0402_5%  [R_0402]  223.27 93.17 0 top
RD30  0_0402_5%  [R_0402]  224.99 95.5 270 top
RD31  0_0402_5%  [R_0402]  227.44 69.3 180 top
RD32  240_0402_1%  [R_0402]  228.02 62.2 0 top
RD38  0_0402_5%  [R_0402]  216.69 93.29 0 top
RD39  0_0402_5%  [R_0402]  216.08 94.77 90 top
RD40  0_0402_5%  [R_0402]  215.09 70.81 0 top
RD41  0_0402_5%  [R_0402]  215.01 93.29 0 top
RD42  0_0402_5%  [R_0402]  215.29 95.68 270 top
RD43  0_0402_5%  [R_0402]  214.25 71.7 270 top
RD44  240_0402_1%  [R_0402]  215.98 59.23 180 top
RD51  470_0402_1%  [R_0402]  252.45 51.7 90 top
RD52  0_0402_5%  [R_0402]  253.18 53.36 0 top
RD54  1K_0402_1%  [R_0402]  224.97 71.85 270 top
RD55  1K_0402_1%  [R_0402]  226.67 70.99 90 top
RD56  24.9_0402_1%  [R_0402]  219 71.94 270 top
RD57  2_0402_1%  [R_0402]  222.43 71.03 180 top
RD58  0_0603_5%  [R_0603]  244.33 96.54 180 top
RD59  0_0603_5%  [R_0603]  229.96 97.46 180 top
RD60  0_0603_5%  [R_0603]  217.65 96.76 90 top
RD61  0_0603_5%  [R_0603]  202.87 93.71 90 top
RD62  0_0402_5%  [R_0402]  253.31 51.67 90 top
RE1  1K_0402_1%  [R_0402]  365.66 34.59 180 top
RE2  1K_0402_1%  [R_0402]  365.66 33.81 180 top
RE3  1M_0402_5%~D  [R_0402]  360.67 42.05 180 bottom
RE4  10K_0402_5%  [R_0402]  356.39 43.94 90 top
RE5  100K_0402_5%  [R_0402]  364.74 35.35 0 top
RE6  100K_0402_5%  [R_0402]  357.28 27.05 180 top
RE7  100K_0402_5%  [R_0402]  357.28 27.86 180 top
RE8  10K_0402_5%  [R_0402]  354.1 27.73 0 top
RE9  15_0402_5%  [R_0402]  370.97 41.5 90 top
RE10  15_0402_5%  [R_0402]  368.35 30.66 270 top
RE11  15_0402_5%  [R_0402]  351.06 35.06 90 top
RE12  10K_0402_5%~D  [R_0402]  367 29.77 90 top
RE13  10K_0402_5%~D  [R_0402]  368.43 42.42 270 top
RE14  10K_0402_5%~D  [R_0402]  369.72 29.77 90 top
RE15  100K_0402_5%  [R_0402]  352.48 41.58 0 top
RE16  100K_0402_5%  [R_0402]  350.42 37.36 270 bottom
RE17  100K_0402_5%  [R_0402]  350.65 41.58 270 top
RE18  0_0201_5%  [R_0201]  361.19 41.31 180 bottom
RE19  0_0201_5%  [R_0201]  359.41 41.31 0 bottom
RE20  10K_0402_5%  [R_0402]  349.53 31.21 90 top
RE21  100K_0402_5%  [R_0402]  350.93 36.73 0 top
RE23  100K_0402_5%  [R_0402]  355.29 44.88 270 top
RE24  0_0603_5%  [R_0603]  294.18 27.75 90 top
RE25  4.7K_0402_1%  [R_0402]  157.99 182.42 270 top
RE28  100K_0402_5%  [R_0402]  176.53 187.86 90 top
RE31  10K_0402_5%~D  [R_0402]  155.32 182.12 90 top
RE33  10K_0201_5%  [R_0201]  103.35 18.25 270 bottom
RE40  4.7K_0402_1%~D  [R_0402]  153.69 183.03 270 top
RE42  4.7K_0402_1%~D  [R_0402]  152.9 182.11 90 top
RE43  4.7K_0402_1%~D  [R_0402]  154.51 183.03 270 top
RE44  4.7K_0402_1%~D  [R_0402]  152.09 182.11 90 top
RE50  0_0603_5%  [R_0603]  269.9 79.27 0 top
RE63  100K_0402_1%  [R_0402]  299.79 27.66 90 top
RE64  100K_0402_1%  [R_0402]  309.93 6.25 0 top
RE66  27K_0402_1%  [R_0402]  310.84 7.03 180 top
RE70  10K_0402_5%  [R_0402]  298.87 28.55 270 top
RE71  0_0402_5%  [R_0402]  100 18.69 270 bottom
RE74  43_0402_1%  [R_0402]  301.65 30.55 90 top
RE75  10K_0402_5%  [R_0402]  289.64 10.01 270 top
RE76  43_0402_1%  [R_0402]  296.11 27.73 90 top
RE77  0_0402_5%  [R0402_0OHM]  300.57 27.66 90 top
RE78  0_0603_5%  [R_0603]  314.19 10.54 270 top
RE79  0_0603_5%  [R_0603]  310.63 25.92 180 top
RE83  10K_0402_5%  [R_0402]  242.19 8.13 180 top
RE84  10K_0402_5%  [R_0402]  303.86 28.65 270 top
RE85  53.6K_0402_5%  [R_0402]  303.07 28.65 270 top
RE90  2.2K_0804_8P4R_5%  [RP_0804_8P4R]  310.32 17.66 0 top
RE100  4.7K_0402_5%  [R_0402]  310.31 20.5 180 top
RE101  4.7K_0402_5%  [R_0402]  310.31 21.28 180 top
RE154  10K_0402_5%  [R_0402]  159.73 169.19 90 top
RE155  1K_0402_1%  [R_0402]  152.94 168.41 90 top
RE156  10K_0402_5%  [R_0402]  152.18 169.33 270 top
RE157  1K_0402_1%  [R_0402]  156.43 171.27 90 top
RE158  10K_0402_5%  [R_0402]  152.16 171.73 270 top
RE160  1K_0402_1%  [R_0402]  158.94 170.91 180 top
RE161  10K_0402_5%  [R_0402]  299.5 45.04 180 bottom
RE200  0_0201_5%  [R_0201-NPM]  234.51 12.91 180 bottom
RE201  10K_0402_5%  [R_0402]  277.84 10.45 270 top
RE202  0_0201_5%  [R_0201-NPM]  234.51 13.55 180 bottom
RE300  10K_0201_1%  [R_0201]  296.6 40.28 0 bottom
RE530  47K_0402_5%  [R_0402]  250.55 7.97 180 top
RE642  4.7K_0402_5%  [R_0402]  250.55 7.21 180 top
RE643  4.7K_0402_5%  [R_0402]  250.49 9.83 180 top
RE645  10K_0402_5%  [R_0402]  301.03 7.2 180 top
RE646  0_0201_5%  [R_0201]  288.47 25.49 0 top
RE647  0_0402_5%  [R_0402-NPM]  297.48 42.72 180 bottom
RE648  0_0402_5%  [R_0402-NPM]  297.48 41.93 180 bottom
RE650  10K_0402_5%  [R_0402]  240.82 10.92 90 top
RE651  0_0402_5%  [R_0402]  352.26 34.64 270 top
RE652  10K_0402_5%  [R_0402]  303.11 48.93 270 bottom
RE653  0_0402_5%  [R_0402]  99.21 18.69 270 bottom
RE654  0_0402_5%  [R_0402]  101.65 13.84 90 top
RE655  0_0402_5%  [R_0402]  100.83 13.84 90 top
RE656  10K_0402_5%  [R_0402]  230.25 15.92 270 bottom
RE657  10K_0402_5%  [R_0402]  364.72 37.39 0 top
RE659  0_0402_5%  [R_0402]  106.7 14.41 90 top
RE660  0_0402_5%  [R_0402]  105.92 14.41 90 top
RE661  10K_0201_5%  [R_0201]  104.57 18.25 270 bottom
RE662  10K_0402_5%  [R_0402]  246.3 5.92 270 top
RE663  10K_0201_5%  [R_0201]  103.96 18.25 270 bottom
RE668  0_0201_5%  [R_0201]  311.64 18.92 0 top
RE669  0_0201_5%  [R_0201]  309.36 19.52 0 top
RE678  0_0201_5%  [R_0201]  287.34 18.29 0 top
RE679  0_0201_5%  [R_0201]  285.67 21.99 0 top
RE680  0_0201_5%  [R_0201]  310.45 14.29 180 top
RE681  0_0201_5%  [R_0201]  288.85 19.54 270 top
RE684  10K_0402_5%  [R_0402]  309.98 13.21 0 top
RE685  10K_0402_5%  [R_0402]  312.34 13.21 0 top
RE688  10K_0402_5%  [R_0402]  286.64 6.63 180 top
RE689  10K_0402_5%  [R_0402]  248.77 14.2 270 top
RE690  10K_0402_5%  [R_0402]  352.04 45.9 270 top
RE691  10K_0402_5%  [R_0402]  352.98 44.22 180 top
RE692  10K_0402_5%  [R_0402]  356.36 26.21 270 top
RE693  10K_0402_5%  [R_0402]  236.75 10.97 180 top
RE694  0_0201_5%  [R_0201]  288.35 16.25 0 top
RE695  10K_0402_5%  [R_0402]  310.31 22.1 180 top
RE696  100K_0402_1%  [R_0402]  312.97 24.81 270 top
RE698  10K_0402_5%  [R_0402]  314.1 19.19 90 top
RE699  10K_0402_5%  [R_0402]  312.14 23.9 90 top
RE700  10K_0402_5%  [R_0402]  311.31 24.81 270 top
RE701  0_0201_5%  [R_0201]  312.71 15.16 0 top
RE702  0_0201_5%  [R_0201]  305.32 19.09 315 bottom
RE703  0_0201_5%  [R_0201]  285.4 10.83 270 top
RE704  47K_0402_5%  [R_0402]  286.64 7.41 180 top
RE705  0_0402_5%  [R_0402]  315.19 9.55 270 top
RE706  0_0402_5%  [R_0402]  303.41 39.84 270 bottom
RE707  10K_0402_5%  [R_0402]  271.03 83.6 270 top
RF1  10K_0402_5%  [R_0402]  89.15 54.71 270 bottom
RF2  10K_0402_5%  [R_0402]  89.99 54.71 270 bottom
RF3  10K_0402_5%  [R_0402]  91.44 54.71 270 bottom
RF4  10K_0402_5%  [R_0402]  375.87 45.79 90 bottom
RF5  10K_0402_5%  [R_0402]  374.95 49.02 270 bottom
RF6  10K_0402_5%  [R_0402]  375.87 49.02 270 bottom
RG555  10K_0201_1%  [R_0201]  182.94 132.23 180 top
RG556  10K_0201_1%  [R_0201]  182.94 132.87 180 top
RH1  1K_0402_1%  [R_0402]  259.16 60.22 0 top
RH2  10K_0402_5%  [R_0402]  271.27 75.39 270 top
RH4  0_0402_5%  [R_0402]  261.98 70.03 0 top
RH5  1K_0402_5%  [R_0402]  299.16 64.16 180 top
RH6  0_0402_5%  [R_0402]  267.74 69.35 90 top
RH7  0_0402_5%  [R_0402]  266.94 69.35 90 top
RH9  100K_0402_5%  [R_0402]  298.27 61.75 0 top
RH11  10K_0402_5%  [R_0402]  272.77 68.91 270 top
RH12  0_0805_5%  [R_0805]  264.95 44.74 270 top
RH14  12.1_0402_1%  [R_0402]  299.69 52.93 0 top
RH15  30_0402_5%  [R_0402]  299.69 53.72 0 top
RH16  33_0402_5%  [R_0402]  288.95 67.82 0 top
RH21  10K_0201_5%  [R_0201]  284.19 74.56 90 top
RH25  10K_0201_5%  [R_0201]  287.25 69.14 90 top
RH26  10K_0201_5%  [R_0201]  287.22 68.53 270 top
RH27  10K_0201_5%  [R_0201]  283.57 69.49 90 top
RH28  10K_0201_5%  [R_0201]  282.96 69.47 90 top
RH29  10K_0201_5%  [R_0201]  275.37 68.37 270 top
RH30  10K_0201_5%  [R_0201]  275.35 67.13 270 top
RH31  0_0402_5%  [R_0402]  275.44 82.4 270 top
RH32  0_0402_5%  [R_0402]  275.55 76.72 90 top
RH38  30_0402_5%  [R_0402]  299.19 57.99 180 top
RH39  20_0402_5%  [R_0402]  299.19 57.2 180 top
RH63  150K_0402_1%  [R_0402]  276.05 70.58 270 top
RH70  10M_0402_5%  [R_0402]  264.46 64.72 90 top
RH71  2.7K_0402_1%  [R_0402]  296.81 47.01 180 top
RH72  1M_0402_5%~D  [R_0402]  297.45 48.33 90 bottom
RH79  620_0402_5%  [R_0402]  299.69 52.14 0 top
RH83  20K_0402_5%~D  [R_0402]  258.93 63.68 0 top
RH84  20K_0402_5%~D  [R_0402]  280.95 81.71 90 bottom
RH85  8.2K_0402_5%  [R_0402]  280.57 72.91 90 bottom
RH88  10K_0402_5%  [R_0402]  262 68.43 0 top
RH89  33_0402_5%  [R_0402]  273.81 74.39 90 top
RH91  33_0201_5%  [R_0201]  295.8 47.87 90 bottom
RH92  33_0201_5%  [R_0201]  295.8 49.66 270 bottom
RH95  4.7K_0402_5%  [R_0402]  282.27 70.43 270 top
RH99  100K_0402_5%  [R_0402]  266.45 51.03 180 top
RH100  4.7K_0402_5%  [R_0402]  265.56 50.26 0 top
RH103  51_0402_5%  [R_0402]  142.02 71.97 180 top
RH104  33_0402_1%  [R_0402]  263.22 58.74 180 top
RH109  113_0402_1%  [R_0402]  295.73 40.99 0 top
RH111  10K_0402_5%~D  [R_0402]  273.58 72.79 270 top
RH130  4.7K_0402_5%~D  [R_0402]  276.05 71.85 90 top
RH135  10K_0402_5%  [R_0402]  274.37 70.61 270 top
RH180  10K_0402_5%  [R_0402]  296.13 62.43 90 top
RH181  20K_0402_1%  [R_0402]  296.75 64.23 180 top
RH182  20K_0402_1%  [R_0402]  296.61 60.78 180 top
RH184  1K_0402_5%  [R_0402]  122.35 80.29 180 bottom
RH185  1K_0402_5%  [R_0402]  122.35 79.47 180 bottom
RH186  1K_0402_5%  [R_0402]  123.74 83.08 180 top
RH187  1K_0402_5%  [R_0402]  122.35 77.92 180 bottom
RH188  1K_0402_5%  [R_0402]  122.35 78.7 180 bottom
RH193  100_0402_1%  [R_0402]  287.06 36.47 180 top
RH199  100K_0402_5%  [R_0402]  280.8 78.86 90 bottom
RH200  0_0201_5%  [R_0201]  335.79 39.52 180 top
RH213  150_0402_1%  [R_0402]  295.82 66.13 0 top
RH214  200_0402_1%  [R_0402]  294.51 65.86 90 bottom
RH215  200_0402_1%  [R_0402]  293.67 65.86 90 bottom
RH216  200_0402_1%  [R_0402]  296.01 67.74 90 top
RH218  10K_0402_5%  [R_0402]  287.81 59.32 90 bottom
RH219  20K_0402_1%  [R_0402]  284.63 56.42 315 bottom
RH220  10K_0402_5%  [R_0402]  286.48 54.56 135 bottom
RH453  1K_0402_5%  [R_0402]  262.89 69.21 180 top
RH460  1K_0402_5%  [R_0402]  280.16 77.21 270 top
RH461  1K_0402_5%  [R_0402]  279.37 77.21 270 top
RH462  1K_0402_5%  [R_0402]  280.72 70.43 270 top
RH463  1K_0402_5%  [R_0402]  279.93 70.43 270 top
RH495  51_0402_5%  [R_0402]  122.82 83.86 0 top
RH501  499_0402_1%  [R_0402]  285.7 71.5 270 bottom
RH502  499_0402_1%  [R_0402]  284.91 71.5 270 bottom
RH506  1M_0402_5%  [R_0402]  275.18 69.7 90 top
RH512  10K_0402_5%  [R_0402]  265.31 55.13 180 top
RH515  8.2K_0402_5%  [R_0402]  270 69.7 90 top
RH516  10K_0402_5%  [R_0402]  286.46 69.44 270 top
RH517  8.2K_0402_5%  [R_0402]  286.49 71.5 270 bottom
RH518  10K_0402_5%~D  [R_0402]  273.58 69.7 90 top
RH520  8.2K_0402_5%  [R_0402]  284.12 71.47 270 bottom
RH521  10K_0402_5%  [R_0402]  282.28 73.12 270 top
RH524  4.7K_0402_5%~D  [R_0402]  277.14 74.75 270 top
RH525  330K_0402_5%  [R_0402]  174.14 28.47 90 top
RH531  1M_0402_5%  [R_0402]  259.87 62.89 180 top
RH533  8.2K_0402_5%  [R_0402]  271.6 69.7 90 top
RH537  10K_0201_5%  [R_0201]  298.67 59.46 0 top
RH545  10K_0402_5%  [R_0402]  270.79 69.7 90 top
RH558  10K_0201_5%  [R_0201]  276.09 66.19 90 top
RH571  8.2K_0402_5%  [R_0402]  298.25 64.95 0 top
RH580  1K_0402_5%  [R_0402]  295.73 40.21 0 top
RH581  1K_0402_5%  [R_0402]  295.73 41.78 0 top
RH588  10K_0402_5%  [R_0402]  282.6 73.81 270 bottom
RH589  10K_0402_5%  [R_0402]  281.84 69.92 90 bottom
RH590  60.4_0402_1%  [R_0402]  296.81 47.8 180 top
RH591  33_0402_5%  [R_0402]  263.86 108.95 180 bottom
RH594  100K_0402_5%  [R_0402]  272.77 70.61 270 top
RH598  0_0402_5%  [R_0402]  282.47 53.29 90 bottom
RH599  0_0402_5%  [R_0402]  286.87 66.62 90 bottom
RH600  100K_0402_5%  [R_0402]  281.51 72.9 90 bottom
RH601  2.2K_0402_5%  [R_0402]  299.19 58.77 180 top
RH602  2.2K_0402_5%  [R_0402]  258.4 57.74 0 top
RH603  4.7K_0402_5%  [R_0402]  296.61 61.57 180 top
RH604  2.2K_0402_5%  [R_0402]  299.19 60.17 180 top
RH605  2.2K_0402_5%  [R_0402]  299.19 60.96 180 top
RH606  2.2K_0402_5%  [R_0402]  299.19 62.53 180 top
RH607  2.2K_0402_5%  [R_0402]  299.19 63.35 180 top
RH613  0_0402_5%  [R0402_0OHM]  296.93 27.73 90 top
RH614  0_0402_5%  [R0402_0OHM]  115.8 170.33 180 top
RH617  0_0402_5%  [R_0402]  114.29 173.95 180 top
RH618  0_0402_5%  [R_0402]  114.29 174.78 180 top
RH619  0_0402_5%  [R_0402]  110.41 170.27 180 top
RH620  0_0402_5%  [R_0402]  276.73 82.29 270 top
RH621  0_0402_5%  [R_0402]  276.73 76.71 90 top
RH622  0_0402_5%  [R_0402]  277.57 81.38 90 top
RH623  0_0402_5%  [R_0402]  278.38 81.38 90 top
RH627  100_0402_1%  [R_0402]  122.82 84.67 0 top
RH628  10K_0402_5%  [R_0402]  299.74 53 270 bottom
RH631  100K_0402_5%  [R_0402]  265.47 59.98 180 top
RH632  100K_0402_5%  [R_0402]  265.47 61.35 180 top
RH633  100K_0402_5%  [R_0402]  265.47 59.19 180 top
RH634  100K_0402_5%  [R_0402]  265.47 62.11 180 top
RH635  20K_0402_5%~D  [R_0402]  255.78 102.32 180 bottom
RH636  20K_0402_5%~D  [R_0402]  262.31 57.95 0 top
RH637  1K_0402_5%  [R_0402]  141.7 71.17 180 top
RH706  8.2K_0402_5%  [R_0402]  349.84 49.3 0 top
RH707  8.2K_0402_5%  [R_0402]  348.82 51.59 0 top
RH722  1K_0201_5%  [R_0201]  355.86 35.14 180 bottom
RH723  1K_0201_5%  [R_0201]  353.64 39.27 180 bottom
RH724  1K_0201_5%  [R_0201]  356.92 35.84 0 bottom
RH725  1K_0201_5%  [R_0201]  354.42 39.94 270 bottom
RH1015  0_0402_5%  [R_0402]  114.84 171.52 90 top
RH1016  0_0402_5%  [R_0402]  281.71 83.74 180 bottom
RH1017  0_0402_5%  [R_0402]  260.25 67.7 90 top
RH1018  0_0402_5%  [R_0402]  261.95 70.81 0 top
RH1021  0_0201_5%  [R_0201]  336.38 39.18 270 top
RH1023  4.7K_0402_5%  [R_0402]  281.49 70.46 270 top
RH1024  100K_0402_5%  [R_0402]  283.17 76.46 90 bottom
RH1025  10K_0402_5%  [R_0402]  271.75 67.24 0 top
RH1026  10K_0402_5%  [R_0402]  280.69 89.3 0 bottom
RH1027  10K_0402_5%  [R_0402]  282.21 86 0 bottom
RL1  0_0402_5%  [R_0402]  175.11 173.63 180 top
RL2  0_0402_5%  [R_0402]  175.11 172.87 180 top
RL3  4.7K_0402_5%  [R_0402]  178.65 158.95 90 top
RL4  4.7K_0402_5%  [R_0402]  178.52 161.24 90 top
RL5  4.7K_0402_5%  [R_0402]  176.35 173.51 0 top
RL6  4.7K_0402_5%  [R_0402]  178.21 177.46 270 top
RL8  4.7K_0402_5%  [R_0402]  177.44 177.46 270 top
RL9  1K_0402_5%  [R_0402]  177.19 174.47 270 bottom
RL10  15K_0402_5%  [R_0402]  176.43 174.47 270 bottom
RL11  2.49K_0402_1%  [R_0402]  184.65 162.08 0 top
RL12  33_0201_1%  [R_0201]  184.11 161.33 90 bottom
RL13  33_0201_1%  [R_0201]  183.54 161.33 90 bottom
RL14  4.7K_0402_1%  [R_0402]  179.42 161.24 90 top
RL15  75_0402_1%~D  [R_0402]  197.2 175.05 270 bottom
RL16  75_0402_1%~D  [R_0402]  198.49 174.47 270 bottom
RL17  75_0402_1%~D  [R_0402]  200.12 174.29 270 bottom
RL18  75_0402_1%~D  [R_0402]  202.02 173.33 180 bottom
RL20  100K_0402_1%  [R_0402]  193.07 163.78 90 bottom
RL21  47.5K_0402_1%  [R_0402]  194.61 165.91 180 bottom
RL22  15K_0402_1%  [R_0402]  194.64 166.08 0 top
RL23  100K_0402_1%  [R_0402]  172.25 161.95 180 top
RL24  20K_0402_1%  [R_0402]  173.76 170.53 270 bottom
RL25  10K_0402_1%  [R_0402]  173.96 168.37 270 bottom
RL30  0_0603_5%  [R_0603]  190.65 174.08 90 top
RL38  0_0603_5%  [R_0603]  189.32 176.17 90 bottom
RL39  0_0603_5%  [R_0603]  181 161.12 180 bottom
RL40  0_0603_5%  [R_0603]  172.88 165.06 180 bottom
RL41  51.1K_0402_1%  [R_0402]  163.81 164.74 180 top
RL42  100K_0402_1%  [R_0402]  159.59 163.92 0 top
RL43  100K_0402_1%  [R_0402]  162.09 164.81 180 top
RL44  0_0603_5%  [R_0603]  181.03 162.43 180 bottom
RL45  0_0603_5%  [R_0603]  187.04 160.55 0 bottom
RL46  0_0603_5%  [R_0603]  176.02 162.39 180 top
RL47  0_0603_5%  [R_0603]  190.08 173.82 90 bottom
RL48  0_0603_5%  [R_0603]  176.94 170.46 180 bottom
RL49  0_0603_5%  [R_0603]  174.27 167.66 90 top
RL50  0_0603_5%  [R_0603]  174.27 170.52 90 top
RL51  10K_0402_5%  [R_0402]  184.94 177.54 270 top
RL52  10K_0402_5%  [R_0402]  185.76 177.54 270 top
RL53  10K_0402_5%  [R_0402]  184.94 177.39 270 bottom
RL54  10K_0402_5%  [R_0402]  185.76 177.39 270 bottom
RL57  0_0402_5%  [R0402_0OHM]  194.73 164.81 180 bottom
RL58  10K_0402_5%  [R_0402]  178.97 177.46 270 top
RL60  4.7K_0402_5%  [R_0402]  170.58 170.27 0 top
RL66  330_0402_5%  [R_0402]  192.48 182.88 180 bottom
RL67  130_0402_5%~D  [R_0402]  213.96 164.95 270 bottom
RL68  130_0402_5%~D  [R_0402]  212.25 164.82 270 bottom
RL69  10K_0402_5%  [R_0402]  167.51 169.67 90 top
RL70  0_0603_5%  [R_0603]  197.51 162.77 180 bottom
RL71  130_0402_5%~D  [R_0402]  212.21 169.01 270 bottom
RM1  0_0201_5%  [R_0201]  160.86 189.01 270 top
RM2  0_0201_5%  [R_0201]  160.27 189.01 270 top
RM5  10K_0402_5%  [R_0402]  171.63 194.56 0 bottom
RM6  10K_0402_5%  [R_0402]  168.2 195.88 90 bottom
RM14  1K_0201_1%  [R_0201]  163.25 182.52 0 bottom
RM17  100K_0402_5%  [R_0402]  168.73 192.87 0 bottom
RM18  2.2_0402_1%  [R_0402]  166.57 174.62 180 bottom
RM20  1K_0402_1%  [R_0402]  162.94 167.59 90 bottom
RM21  1K_0402_1%  [R_0402]  166.67 169.7 180 bottom
RM23  1K_0201_1%  [R_0201]  178.07 183.65 180 bottom
RM25  475_0402_1%  [R_0402]  162.72 178.09 270 bottom
RM26  1K_0201_1%  [R_0201]  178.07 182.9 180 bottom
RM27  33_0402_1%  [R_0402]  159.8 178.74 270 bottom
RM28  33_0402_1%  [R_0402]  159.02 178.74 270 bottom
RM29  49.9_0402_1%  [R_0402]  159.87 179.56 180 bottom
RM38  49.9_0402_1%  [R_0402]  160.6 179.56 0 bottom
RM41  100K_0402_5%  [R_0402]  182.27 188.03 90 top
RM42  470K_0402_5%  [R_0402]  185.62 189.13 0 top
RM61  20K_0402_5%  [R_0402]  178.26 179.59 180 bottom
RM62  1K_0201_1%  [R_0201]  177.76 176.99 180 bottom
RM64  1K_0201_1%  [R_0201]  177.48 181.76 0 bottom
RM66  1K_0201_1%  [R_0201]  177.48 182.34 0 bottom
RM70  1K_0201_1%  [R_0201]  163.43 177.45 90 bottom
RM72  10K_0201_5%  [R_0201]  163.83 183.67 180 bottom
RM75  1K_0201_1%  [R_0201]  177.76 178.71 180 bottom
RM76  1K_0201_1%  [R_0201]  164.02 178.13 0 bottom
RM79  1K_0201_1%  [R_0201]  177.76 178.13 180 bottom
RM81  1K_0201_1%  [R_0201]  163.85 178.71 0 bottom
RM82  1K_0201_1%  [R_0201]  178.07 184.21 180 bottom
RM84  1K_0201_1%  [R_0201]  163.85 179.27 0 bottom
RM85  1K_0201_1%  [R_0201]  178.07 184.8 180 bottom
RM86  1K_0201_1%  [R_0201]  177.76 177.54 180 bottom
RM87  10K_0201_5%  [R_0201]  163.83 183.08 180 bottom
RM91  549_0402_1%  [R_0402]  161.9 192.63 90 bottom
RM92  100K_0402_5%~D  [R_0402]  161.9 191.87 270 bottom
RM93  100_0402_1%  [R_0402]  160.96 190.19 0 bottom
RM94  100K_0402_5%~D  [R_0402]  159.89 193.65 180 bottom
RM96  4.7K_0402_5%  [R_0402]  166.67 170.48 180 bottom
RN1  0_0402_5%  [R_0402]  338.49 37.93 180 top
RN6  75K_0402_1%  [R_0402]  356.65 36.84 90 bottom
RN7  100K_0201_5%  [R_0201]  354.84 38.44 180 bottom
RN8  75K_0402_1%  [R_0402]  354.42 40.78 90 bottom
RN9  100K_0201_5%  [R_0201]  350.74 41.21 270 bottom
RN20  0_0805_5%  [R_0805]  335.3 30.62 90 top
RN30  100K_0402_5%  [R_0402]  342.54 41.95 270 top
RN101  0_0201_5%  [R_0201]  346.72 38.25 180 bottom
RN102  0_0201_5%  [R_0201]  346.72 37.67 180 bottom
RN103  0_0201_5%  [R_0201]  346.72 36.17 180 bottom
RN104  0_0201_5%  [R_0201]  346.72 36.75 180 bottom
